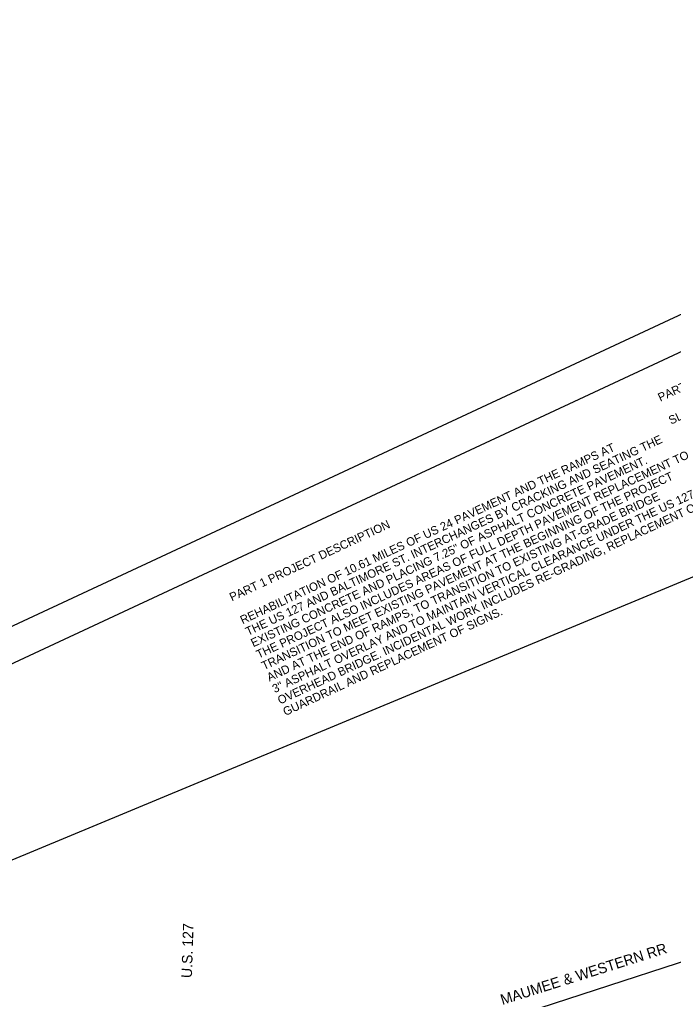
# Model space of a CAD drawing. Extents: x -310467766 to 17062430, y -322263100 to 8322522.
# Drawn here: x 1394957 to 1397865, y 574364 to 578688 of the extents above; entities that cross this region are included whole.
import ezdxf

# ---------------------------------------------------------------- set-up
doc = ezdxf.new("R2010")
doc.units = 0
for name, color, linetype in [('Level 14', 7, 'Continuous'), ('Level 40', 7, 'Continuous'), ('SC_Scratch1', 7, 'Continuous'), ('SH_Border', 7, 'Continuous'), ('SH_Cut_Line', 7, 'Continuous')]:
    doc.layers.add(name, color=color, linetype=linetype)

msp = doc.modelspace()

# ---------------------------------------------------------------- linework, layer by layer
at = {"layer": 'Level 14'}
msp.add_lwpolyline([(1396045.7, 573892.7), (1398068.9, 574551.5), (1399780.9, 575107.6), (1401168.4, 575558.4)], dxfattribs=at)
at = {"layer": 'SC_Scratch1'}
msp.add_lwpolyline([(1392212.4, 573822.1), (1393676.3, 570715.4), (1396857.5, 571041.4), (1399761.2, 572912.7), (1399601.4, 573251.9), (1400998.4, 575913.7), (1400551.7, 577289.3)], close=True, dxfattribs=at)
at = {"layer": 'SH_Border'}
msp.add_lwpolyline([(1391939.2, 574432), (1400639.7, 578489.1), (1403302.2, 572779.4), (1394601.7, 568722.3)], close=True, dxfattribs=at)
at = {"layer": 'SH_Cut_Line'}
msp.add_lwpolyline([(1394257.2, 568396.1), (1403501.6, 572706.8), (1400712.3, 578688.5), (1391467.9, 574377.8)], close=True, dxfattribs=at)

# ---------------------------------------------------------------- texts
at = {"layer": 'Level 40'}
for s, height, rotation, p in [('SLIDE REPAIR BY RECONSTRUCTING AND BENCHING THE EMBANKMENT', 37.5, 25, (1397853.9, 576885.8)), ('PART 2 PROJECT DESCRIPTION', 37.5, 25, (1397806.3, 576987.8)), ('THE US 127 AND BALTIMORE ST. INTERCHANGES BY CRACKING AND SEATING THE', 37.5, 25, (1395972.9, 575946.6)), ('REHABILITATION OF 10.61 MILES OF US 24 PAVEMENT AND THE RAMPS AT', 37.5, 25, (1395949.1, 575997.6)), ('THE PROJECT ALSO INCLUDES AREAS OF FULL DEPTH PAVEMENT REPLACEMENT TO', 37.5, 25, (1396020.4, 575844.6)), ('EXISTING CONCRETE AND PLACING 7.25" OF ASPHALT CONCRETE PAVEMENT.', 37.5, 25, (1395996.6, 575895.6)), ('TRANSITION TO MEET EXISTING PAVEMENT AT THE BEGINNING OF THE PROJECT', 37.5, 25, (1396044.2, 575793.7)), ('AND AT THE END OF RAMPS, TO TRANSITION TO EXISTING AT-GRADE BRIDGE', 37.5, 25, (1396067.9, 575742.7)), ('3" ASPHALT OVERLAY AND TO MAINTAIN VERTICAL CLEARANCE UNDER THE US 127', 37.5, 25, (1396091.7, 575691.7)), ('OVERHEAD BRIDGE. INCIDENTAL WORK INCLUDES RE-GRADING, REPLACEMENT OF', 37.5, 25, (1396115.5, 575640.7)), ('PART 1 PROJECT DESCRIPTION', 37.5, 25, (1395901.5, 576099.5)), ('GUARDRAIL AND REPLACEMENT OF SIGNS.', 37.5, 25, (1396139.3, 575589.7)), ('U.S. 127', 46.8, 88.1676, (1395723.5, 574424)), ('MAUMEE & WESTERN RR', 46.8, 17.5171, (1397104.2, 574304.5))]:
    msp.add_text(s, height=height, rotation=rotation, dxfattribs=at).set_placement(p)

doc.saveas('drawing.dxf')
